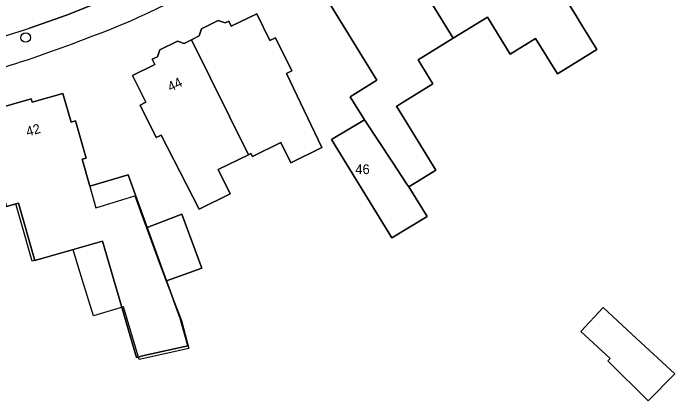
# Model space of a CAD drawing. Extents: x 161347 to 161881, y 382161 to 382804.
# Drawn here: x 161600.2 to 161668.5, y 382231.6 to 382271.6 of the extents above; entities that cross this region are included whole.
import ezdxf

# ---------------------------------------------------------------- set-up
doc = ezdxf.new("R2010")
doc.units = 0
for name, color, linetype in [('IMGEO_Boom', 7, 'Continuous'), ('IMGEO_Erf', 7, 'Continuous'), ('IMGEO_Pand', 7, 'Continuous'), ('IMGEO_Pand_nummerreeks', 7, 'Continuous'), ('IMGEO_Pand_vergunning_verleend', 7, 'Continuous'), ('IMGEO_Rijbaan_lokaal_open', 7, 'Continuous'), ('IMGEO_Voetpad_open', 7, 'Continuous')]:
    doc.layers.add(name, color=color, linetype=linetype)

msp = doc.modelspace()

# ---------------------------------------------------------------- linework, layer by layer
at = {"layer": 'IMGEO_Boom'}
msp.add_circle((161601.505, 382269.102), 0.489, dxfattribs=at)
at = {"layer": 'IMGEO_Erf'}
msp.add_lwpolyline([(161655.579, 382275.783), (161658.197, 382271.524), (161658.721, 382270.672), (161660.453, 382267.871), (161656.377, 382265.35), (161654.12, 382269.001), (161651.508, 382267.386), (161649.162, 382271.205), (161645.623, 382269.03), (161641.996, 382266.802), (161643.529, 382264.307), (161640.191, 382262.256), (161639.874, 382262.061), (161639.781, 382262.004), (161641.053, 382259.934), (161643.843, 382255.393), (161641.033, 382253.694), (161642.926, 382250.613), (161639.3, 382248.425), (161633.057, 382258.588), (161636.457, 382260.596), (161634.981, 382262.997), (161637.748, 382264.697), (161632.722, 382272.877)], dxfattribs=at)
for points in [[(161622.617, 382252.966), (161619.399, 382251.373), (161615.494, 382259.035), (161614.982, 382258.782), (161613.324, 382262.134), (161613.902, 382262.42), (161612.528, 382265.198), (161614.828, 382266.336), (161614.572, 382266.854), (161615.118, 382267.124), (161615.358, 382267.833), (161617.172, 382268.73), (161617.852, 382268.5), (161618.625, 382268.882), (161619.4, 382269.266), (161619.647, 382269.995), (161621.379, 382270.852), (161622.081, 382270.615), (161622.462, 382270.803), (161622.726, 382270.268), (161625.345, 382271.563), (161626.714, 382268.796), (161627.272, 382269.073), (161628.965, 382265.65), (161628.434, 382265.387), (161632.076, 382257.752), (161628.876, 382256.17), (161627.836, 382258.273), (161624.901, 382256.822), (161624.753, 382257.122), (161624.511, 382257.002), (161621.386, 382255.456)], [(161609.426, 382248.067), (161602.445, 382246.079), (161600.76, 382251.997), (161599.525, 382251.645), (161598.278, 382256.02), (161599.239, 382256.294), (161597.745, 382261.54), (161602.072, 382262.772), (161602.175, 382262.412), (161605.355, 382263.317), (161606.198, 382260.356), (161606.65, 382260.485), (161607.742, 382256.649), (161607.331, 382256.532), (161608.119, 382253.767), (161612.081, 382254.919), (161614.045, 382249.488), (161617.62, 382250.853), (161619.691, 382245.273), (161616.046, 382243.956), (161617.443, 382240.091), (161618.229, 382237.27), (161613.868, 382236.274), (161612.952, 382236.065)], [(161661.1, 382241.201), (161664.103, 382238.409), (161668.49, 382234.358), (161665.761, 382231.578), (161661.574, 382235.689), (161661.812, 382235.945), (161658.81, 382238.737)]]:
    msp.add_lwpolyline(points, close=True, dxfattribs=at)
for centre, radius, start, end in [((161578.493, 382349.06), 85.227, 289.88576, 300.97211), ((161564.574, 382378.018), 117.238, 281.81391, 291.46888)]:
    msp.add_arc(centre, radius, start, end, dxfattribs=at)
at = {"layer": 'IMGEO_Pand'}
for points in [[(161649.162, 382271.205), (161651.508, 382267.386), (161654.12, 382269.001), (161656.377, 382265.35), (161660.453, 382267.871), (161658.721, 382270.672), (161658.197, 382271.524), (161655.579, 382275.783), (161654.477, 382277.536), (161651.7, 382275.829), (161647.731, 382282.286), (161646.932, 382281.795), (161646.693, 382282.184), (161646.127, 382281.836), (161644.704, 382284.152), (161641.895, 382282.426), (161641.317, 382283.367), (161638.045, 382281.357), (161645.623, 382269.03)], [(161645.623, 382269.03), (161638.045, 382281.357), (161634.538, 382279.202), (161635.132, 382278.235), (161632.231, 382276.452), (161633.687, 382274.081), (161633.155, 382273.753), (161633.427, 382273.31), (161632.722, 382272.877), (161637.748, 382264.697), (161634.981, 382262.997), (161636.457, 382260.596), (161639.362, 382256.214), (161640.853, 382253.965), (161641.033, 382253.694), (161643.843, 382255.393), (161641.053, 382259.934), (161639.781, 382262.004), (161639.874, 382262.061), (161640.191, 382262.256), (161643.529, 382264.307), (161641.996, 382266.802)], [(161618.625, 382268.882), (161624.511, 382257.002), (161624.753, 382257.122), (161624.901, 382256.822), (161627.836, 382258.273), (161628.876, 382256.17), (161632.076, 382257.752), (161628.434, 382265.387), (161628.965, 382265.65), (161627.272, 382269.073), (161626.714, 382268.796), (161625.345, 382271.563), (161622.726, 382270.268), (161622.462, 382270.803), (161622.081, 382270.615), (161621.379, 382270.852), (161619.647, 382269.995), (161619.4, 382269.266)], [(161618.625, 382268.882), (161617.852, 382268.5), (161617.172, 382268.73), (161615.358, 382267.833), (161615.118, 382267.124), (161614.572, 382266.854), (161614.828, 382266.336), (161612.528, 382265.198), (161613.902, 382262.42), (161613.324, 382262.134), (161614.982, 382258.782), (161615.494, 382259.035), (161619.399, 382251.373), (161622.617, 382252.966), (161621.386, 382255.456), (161624.511, 382257.002)], [(161612.081, 382254.919), (161608.119, 382253.767), (161607.331, 382256.532), (161607.742, 382256.649), (161606.65, 382260.485), (161606.198, 382260.356), (161605.355, 382263.317), (161602.175, 382262.412), (161602.072, 382262.772), (161597.745, 382261.54), (161599.239, 382256.294), (161598.278, 382256.02), (161599.525, 382251.645), (161600.76, 382251.997), (161602.445, 382246.079), (161609.426, 382248.067), (161612.952, 382236.065), (161613.868, 382236.274), (161618.229, 382237.27), (161617.443, 382240.091), (161616.046, 382243.956), (161614.045, 382249.488)], [(161636.457, 382260.596), (161633.057, 382258.588), (161639.3, 382248.425), (161642.926, 382250.613), (161641.033, 382253.694), (161640.853, 382253.965), (161639.362, 382256.214)], [(161617.62, 382250.853), (161614.045, 382249.488), (161616.046, 382243.956), (161619.691, 382245.273)], [(161664.103, 382238.409), (161661.1, 382241.201), (161658.81, 382238.737), (161661.812, 382235.945), (161661.574, 382235.689), (161665.761, 382231.578), (161668.49, 382234.358)]]:
    msp.add_lwpolyline(points, close=True, dxfattribs=at)
at = {"layer": 'IMGEO_Pand_vergunning_verleend'}
msp.add_lwpolyline([(161597.745, 382261.54), (161602.072, 382262.772), (161602.175, 382262.412), (161605.355, 382263.317), (161606.198, 382260.356), (161606.65, 382260.485), (161607.742, 382256.649), (161607.331, 382256.532), (161608.761, 382251.512), (161612.782, 382252.741), (161613.772, 382250), (161613.97, 382249.459), (161615.147, 382246.248), (161615.994, 382243.937), (161617.578, 382239.875), (161618.343, 382236.984), (161613.233, 382235.848), (161611.609, 382241.295), (161608.49, 382240.369), (161607.363, 382244.016), (161606.394, 382247.186), (161602.177, 382245.985), (161601.034, 382250), (161600.487, 382251.919), (161599.525, 382251.645)], dxfattribs=at)
at = {"layer": 'IMGEO_Rijbaan_lokaal_open'}
msp.add_lwpolyline([(161601.914, 382270.088), (161605.711, 382271.429), (161609.273, 382272.828)], dxfattribs=at)
msp.add_arc((161565.149, 382379.907), 115.809, 283.96622, 288.50925, dxfattribs=at)
at = {"layer": 'IMGEO_Voetpad_open'}
msp.add_lwpolyline([(161609.273, 382272.828), (161605.711, 382271.429), (161601.914, 382270.088)], dxfattribs=at)
for centre, radius, start, end in [((161578.493, 382349.06), 85.227, 289.88576, 300.97211), ((161565.149, 382379.907), 115.809, 283.96622, 288.50925), ((161564.574, 382378.018), 117.238, 281.81391, 291.46888)]:
    msp.add_arc(centre, radius, start, end, dxfattribs=at)

# ---------------------------------------------------------------- texts
at = {"layer": 'IMGEO_Pand_nummerreeks'}
for s, rotation, p in [('44', 26.40928, (161616.45, 382263.485)), ('42', 15.88812, (161601.701, 382258.866))]:
    msp.add_text(s, height=1, rotation=rotation, dxfattribs=at).set_placement(p)
msp.add_text('46', height=1, dxfattribs=at).set_placement((161635.52, 382254.999))

doc.saveas('drawing.dxf')
